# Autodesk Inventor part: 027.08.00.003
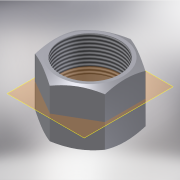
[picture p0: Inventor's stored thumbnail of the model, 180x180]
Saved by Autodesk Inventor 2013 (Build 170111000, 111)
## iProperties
Shininess: 25.0
Length Units: 11269
Angle Units: 11279
Time Units: 11290
Mass Units: 11283
Length Display Precision: 3
Angle Display Precision: 2
Created: 2001-07
Part Number: 027.08.00.003
Material: Steel, Mild
Document SubType Name: Modeling
Designer: SOleg
Description: Гайка
Mass: 73.7541 g
Surface Area: 59.8855 cm^2
Volume: 9.38347 cm^3
Density: 7.86 g/cm^3
Density: 0.0
Volumn: 0.0
Area: 0.0
PropertySet Name: Model Information
Control State: 0
Master: False
Checked Out: False
Checked Out Date: 2008-10-15
Last Check In Date: 2008-10-15
Author: SOleg
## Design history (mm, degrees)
sketch "Sketch1"
  geometry: L1 (145.001, 133.67)-(145.001, 152.145); L2 (129.001, 124.432)-(145.001, 133.67); L3 (113.001, 133.67)-(129.001, 124.432); L4 (113.001, 152.145)-(113.001, 133.67); L5 (129.001, 161.383)-(113.001, 152.145); L6 (145.001, 152.145)-(129.001, 161.383); C1 r 16 at (129.001, 142.907); 1 further point
  constraints: 12 end point, 6 tangent, 5 equal length, 2 parallel, 2 vertical, 1 centre point, 1 coincident
  dimensions: "d43" = 32 diameter of C1
extrude "ExtrusionBlind1" new body sketch "Sketch1" distance "d18" = 26; taper "d19" = 0 deg
sketch "Sketch2"
  geometry: C1 r 10 at (-129.001, 142.907); 1 further point
  constraints: 1 centre point, 1 coincident
  dimensions: "d22" = 20 diameter of C1
extrude "ExtrusionBlind2" cut sketch "Sketch2" distance "d23" = 6; taper "d24" = 0 deg
sketch "Sketch3"
  geometry: C1 r 13.85 at (0, 0); C2 r 10 at (0, 0) reference
  constraints: 1 centre point, 1 coincident
  dimensions: "d27" = 27.7 diameter of C1
extrude "ExtrusionBlind3" cut sketch "Sketch3" distance "d28" = 3.8; taper "d29" = 0 deg
sketch "Sketch4"
  geometry: C1 r 13.5 at (0, 0); C2 r 10 at (0, 0) reference
  constraints: 1 centre point, 1 coincident
  dimensions: "d32" = 27 diameter of C1
extrude "ExtrusionBlind4" cut sketch "Sketch4" distance "d33" = 30; taper "d34" = 0 deg
thread "Thread1" dims "d35" = 10, "d36" = 0
sketch "Эскиз5"
  geometry: C1 r 10 at (-129.001, 142.907) reference; C2 r 15 at (-129.001, 142.907); C3 r 25 at (-129.001, 142.907)
  constraints: 2 centre point, 2 coincident
  dimensions: "d37" = 30 diameter of C2; "d39" = 50 diameter of C3
extrude "Выдавливание5" cut sketch "Эскиз5" stored distance "d40" = 10; taper "d41" = -60 deg
node "РабПлоскость1"
mirror "ЗеркОтобр1"
body "Solid1"
other parameters: "d0" = 32 (derived), "d2" = 32 (derived), "d4" = 32 (derived), "d6" = 32 (derived), "d8" = 36.95 (derived), "d10" = 36.95 (derived), "d12" = 36.95 (derived), "d14" = 0 (derived), "d16" = 18.38 (derived), "d20" = 0, "d25" = 0, "d26" = 27.7 (derived), "d30" = 0, "d31" = 27 (derived), "d42" = -13
